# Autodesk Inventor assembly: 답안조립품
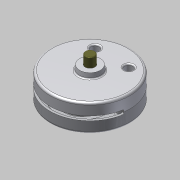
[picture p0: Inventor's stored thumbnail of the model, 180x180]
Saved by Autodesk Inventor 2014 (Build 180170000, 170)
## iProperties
Created: 2015-06
Part Number: 답안조립품
Document SubType Name: Assembly
Designer: MYHOME
Author: MYHOME
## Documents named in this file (6)
- C:\Documents and Settings\MYHOME\바탕 화면\450631V1029\답안조립품.iam
- C:\Documents and Settings\MYHOME\바탕 화면\450631V1029\본체.ipt
- C:\Documents and Settings\MYHOME\바탕 화면\450631V1029\덮개.ipt
- C:\Documents and Settings\MYHOME\바탕 화면\450631V1029\축.ipt
- C:\Documents and Settings\MYHOME\바탕 화면\450631V1029\베어링62_22.ipt
- C:\Documents and Settings\MYHOME\바탕 화면\450631V1029\슬라이더2.ipt
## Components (2 placed, 1 different names)
1. KS B 2023 62/22 - 22 x 50 x 14:1
2. KS B 2023 62/22 - 22 x 50 x 14:2
